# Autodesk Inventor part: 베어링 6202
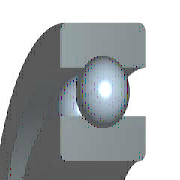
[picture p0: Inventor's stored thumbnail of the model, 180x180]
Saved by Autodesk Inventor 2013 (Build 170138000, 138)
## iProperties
IsCustomPart: 1
Created: 2015-09
Part Number: 베어링 6202
Material: 강철, 연강
Description: 깊은 그루브 볼 베어링
Document SubType Name: Modeling
Standard: KS B 2023
Designer: mduedu
Standards Organization: KS
Language: ko-KR
Size Designation: 6202 - 15 x 35 x 11
Categories: <MemberInstance><Categories><Category DisplayName="샤프트 부품" InternalName="7f7aeb1f-a693-4053-b835-cee3144e0d98" Mnemonic="SHFT"><Category DisplayName="베어링" Inter
Density: 7.86 g/cm^3
Mass: 45.8725 g
Surface Area: 51.5584 cm^2
Volume: 5.83619 cm^3
Author: mduedu
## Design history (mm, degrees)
sketch "스케치" dims "d0" = 5.2 (= -0.26 x WD + 0.26 x BD)
  geometry: L1 (2.9, 12.5)-(8.1, 12.5); L2 (5.5, 12.5)-(5.5, 9.9); L3 (5.5, 12.5)-(5.5, 15.1); L4 (3.568, 10.76)-(0, 10.76); L5 (0, 7.5)-(11, 7.5); L6 (3.568, 14.24)-(0, 14.24); L7 (0, 17.5)-(11, 17.5); L8 (11, 7.5)-(11, 10.76); L9 (7.432, 10.76)-(11, 10.76); L10 (7.432, 14.24)-(11, 14.24); L11 (11, 17.5)-(11, 14.24); L12 (-1.4, 0)-(8.4, 0) reference; L13 (0, -0.3)-(0, 5.3) reference
  constraints: 22 end point, 4 point on line, 2 collinear, 2 perpendicular, 2 symmetric about line, 1 midpoint, 1 parallel, 14 other
  dimensions: "d9" = 15 diameter of L5 L12 (= WD); "d11" = 35 diameter of L7 L12 (= BD); "d12" = 11 distance between parallel lines of L8 L13 (= KB); "d13" = 21.52 diameter of L9 L12 (= 0.326 x BD + 0.674 x WD)
revolve "본체" stored, may be unused: angle "d6" = 90 deg
revolve "볼" stored, may be unused: angle "d7" = 90 deg
pattern_circular "IDS_ARRAYBALL[SIMPL:T]" dims angle "d3" = 360 deg
body "Solid1"
fillet "모깎기1" dims "d1" = 0.6 (= KRS)
other parameters: "WD" = 15 [user parameter; used in 5 equation terms], "BD" = 35 [user parameter; used in 5 equation terms], "KB" = 11 [user parameter; used in 1 equation term], "KRS" = 0.6 [user parameter; used in 1 equation term], "d4" = 0, "d5" = 0, "d8" = 0, "d14" = 0, "d15" = 0, "BBA" = 0 [user parameter], "BC0" = 3750000 [user parameter], "BC" = 7800000 [user parameter], "BR" = 17.5 (= 0.5 x BD) [user parameter], "WR" = 7.5 (= 0.5 x WD) [user parameter]
